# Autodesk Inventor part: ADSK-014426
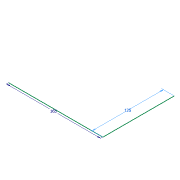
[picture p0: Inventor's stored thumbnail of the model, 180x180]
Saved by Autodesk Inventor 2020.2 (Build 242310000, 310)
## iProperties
Created: 2019-11
Part Number: ADSK-014426
Material: 1.0501 C35
Document SubType Name: Modeling
Designer: lutzd
Density: 7.84 g/cm^3
Appearance: Stahl
VLDS_Profile: Default Part
VLDS_TimeStamp: 2016-07-29
VLDS_FailCnt: 0
VLDS_AcceptCnt: 0
Dimensions: 0x0x0 mm
Mass: 0 kg
DocNumber: ADSK-014426
Folder: 01 - Themengebiete\Simplification\01 - Packaging machine\Parts\
VDS_Category: 3D Komponenten
VDS_NumSchm: Autodesk
VLT_Material: 1.0501 C35
Title: skeleton
Author: lutzd
Revision Number: -
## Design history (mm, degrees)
sketch "Skizze1"
  geometry: L1 (0, 0)-(-165, 0); L2 (0, 0)-(0, 125)
  constraints: 4 end point, 1 horizontal, 1 vertical
  dimensions: "d0" = 165 dimension on L1.start L1.end L1 L2.end L2; "d0" = 165 distance of L1.start L1.end; "d1" = 125 distance of L1.start L2.end
